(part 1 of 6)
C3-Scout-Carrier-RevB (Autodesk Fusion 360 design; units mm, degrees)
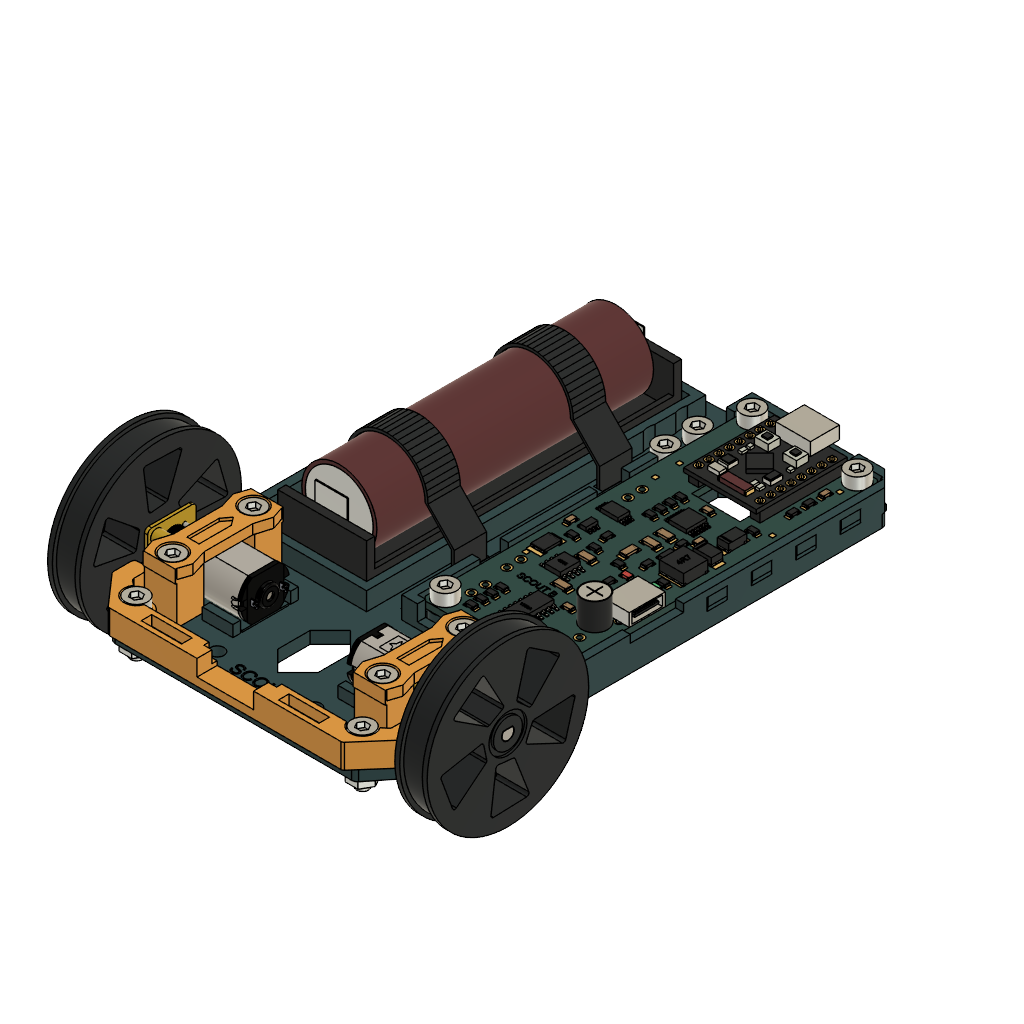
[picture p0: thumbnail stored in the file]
description: Part Number
part number: mmgm-logo-step
part number: reg28a01
part number: drv8833-dual-motor-driver-carrier-step
part number: pololu-3.3v-step-up_step-down-voltage-regulator-s7v8f3
parameter "base_thickness" = 3 comment "Floor thickness"
parameter "wheel_diameter" = 40 comment "Outside diameter"
parameter "wheel_width" = 8 comment "Wheel width"
parameter "shaft_bore" = 3.15 comment "Print coupon before wheels"
parameter "d280" = 1.35
parameter "d466" = 2.4
base_feature "Base Feature1" sketch "Bottom plated annuli 0.95 profiles"
sketch "Tapered monocoque floor outline" plane through (0, 0, 0) normal (0, 0, 1) x axis (1, 0, 0)
  line L1 (30, -53) -> (-30, -53)
  line L2 (38, -43) -> (30, -53)
  line L3 (38, -19) -> (38, -43)
  line L4 (36, -8) -> (38, -19)
  line L5 (36, 50) -> (36, -8)
  line L6 (28, 68) -> (36, 50)
  line L7 (-28, 68) -> (28, 68)
  line L8 (-36, 50) -> (-28, 68)
  line L9 (-36, -8) -> (-36, 50)
  line L10 (-38, -19) -> (-36, -8)
  line L11 (-38, -43) -> (-38, -19)
  line L12 (-30, -53) -> (-38, -43)
extrude "Extrude1" new body sketch "Tapered monocoque floor outline" along normal blind 3 (= "base_thickness")
fillet "Fillet1" radius 2
sketch "Side gill 1 outline" plane through (0, 0, 0) normal (0, 0, 1) x axis (1, 0, 0)
  line L1 (33.5, -8) -> (30.3, -10)
  line L2 (33.5, -3) -> (33.5, -8)
  line L3 (30.3, -5) -> (33.5, -3)
  line L4 (30.3, -10) -> (30.3, -5)
extrude "Extrude2" cut sketch "Side gill 1 outline" along normal blind 3
sketch "Side gill 2 outline" plane through (0, 0, 0) normal (0, 0, 1) x axis (1, 0, 0)
  line L1 (33.5, 5) -> (30.3, 3)
  line L2 (33.5, 10) -> (33.5, 5)
  line L3 (30.3, 8) -> (33.5, 10)
  line L4 (30.3, 3) -> (30.3, 8)
extrude "Extrude3" cut sketch "Side gill 2 outline" along normal blind 3
sketch "Side gill 3 outline" plane through (0, 0, 0) normal (0, 0, 1) x axis (1, 0, 0)
  line L1 (33.5, 18) -> (30.3, 16)
  line L2 (33.5, 23) -> (33.5, 18)
  line L3 (30.3, 21) -> (33.5, 23)
  line L4 (30.3, 16) -> (30.3, 21)
extrude "Extrude4" cut sketch "Side gill 3 outline" along normal blind 3
sketch "Side gill 4 outline" plane through (0, 0, 0) normal (0, 0, 1) x axis (1, 0, 0)
  line L1 (33.5, 31) -> (30.3, 29)
  line L2 (33.5, 36) -> (33.5, 31)
  line L3 (30.3, 34) -> (33.5, 36)
  line L4 (30.3, 29) -> (30.3, 34)
extrude "Extrude5" cut sketch "Side gill 4 outline" along normal blind 3
sketch "Side gill 5 outline" plane through (0, 0, 0) normal (0, 0, 1) x axis (1, 0, 0)
  line L1 (33.5, 44) -> (30.3, 42)
  line L2 (33.5, 49) -> (33.5, 44)
  line L3 (30.3, 47) -> (33.5, 49)
  line L4 (30.3, 42) -> (30.3, 47)
extrude "Extrude6" cut sketch "Side gill 5 outline" along normal blind 3
sketch "Battery floor window 1 outline" plane through (0, 0, 0) normal (0, 0, 1) x axis (1, 0, 0)
  line L1 (-7, -12) -> (-25, -12)
  line L2 (-7, -2) -> (-7, -12)
  line L3 (-10, 0) -> (-7, -2)
  line L4 (-25, 0) -> (-10, 0)
  line L5 (-25, -12) -> (-25, 0)
extrude "Extrude7" cut sketch "Battery floor window 1 outline" along normal blind 3
sketch "Battery floor window 2 outline" plane through (0, 0, 0) normal (0, 0, 1) x axis (1, 0, 0)
  line L1 (-7, 11) -> (-25, 11)
  line L2 (-7, 24) -> (-7, 11)
  line L3 (-10, 26) -> (-7, 24)
  line L4 (-25, 26) -> (-10, 26)
  line L5 (-25, 11) -> (-25, 26)
extrude "Extrude8" cut sketch "Battery floor window 2 outline" along normal blind 3
sketch "Battery floor window 3 outline" plane through (0, 0, 0) normal (0, 0, 1) x axis (1, 0, 0)
  line L1 (-7, 29) -> (-25, 29)
  line L2 (-7, 34) -> (-7, 29)
  line L3 (-10, 36) -> (-7, 34)
  line L4 (-25, 36) -> (-10, 36)
  line L5 (-25, 29) -> (-25, 36)
extrude "Extrude9" cut sketch "Battery floor window 3 outline" along normal blind 3
sketch "Battery floor window 4 outline" plane through (0, 0, 0) normal (0, 0, 1) x axis (1, 0, 0)
  line L1 (-7, 47) -> (-25, 47)
  line L2 (-7, 58) -> (-7, 47)
  line L3 (-10, 60) -> (-7, 58)
  line L4 (-25, 60) -> (-10, 60)
  line L5 (-25, 47) -> (-25, 60)
extrude "Extrude10" cut sketch "Battery floor window 4 outline" along normal blind 3
sketch "Electronics cable window 1 outline" plane through (0, 0, 0) normal (0, 0, 1) x axis (1, 0, 0)
  line L1 (25, -11) -> (12, -11)
  line L2 (27, -9) -> (25, -11)
  line L3 (27, 8) -> (27, -9)
  line L4 (12, 8) -> (27, 8)
  line L5 (12, -11) -> (12, 8)
extrude "Extrude11" cut sketch "Electronics cable window 1 outline" along normal blind 3
sketch "Electronics cable window 2 outline" plane through (0, 0, 0) normal (0, 0, 1) x axis (1, 0, 0)
  line L1 (25, 18) -> (12, 18)
  line L2 (27, 20) -> (25, 18)
  line L3 (27, 31) -> (27, 20)
  line L4 (12, 31) -> (27, 31)
  line L5 (12, 18) -> (12, 31)
extrude "Extrude12" cut sketch "Electronics cable window 2 outline" along normal blind 3
sketch "Electronics cable window 3 outline" plane through (0, 0, 0) normal (0, 0, 1) x axis (1, 0, 0)
  line L1 (25, 45) -> (12, 45)
  line L2 (27, 47) -> (25, 45)
  line L3 (27, 59) -> (27, 47)
  line L4 (12, 59) -> (27, 59)
  line L5 (12, 45) -> (12, 59)
extrude "Extrude13" cut sketch "Electronics cable window 3 outline" along normal blind 3
work_plane "WorkPlane1" AlongDistance 3 ExtraOffset 0
sketch "Sculpted side rail -1 outline" plane through (0, 0, 3) normal (0, 0, 1) x axis (1, 0, 0)
  line L1 (-36, -14) -> (-33.8, -14)
  line L2 (-36, 49) -> (-36, -14)
  line L3 (-29, 64) -> (-36, 49)
  line L4 (-27, 64) -> (-29, 64)
  line L5 (-33.8, 48) -> (-27, 64)
  line L6 (-33.8, -14) -> (-33.8, 48)
extrude "Extrude14" add sketch "Sculpted side rail -1 outline" along normal blind 4.5
work_plane "WorkPlane2" AlongDistance 3 ExtraOffset 0
sketch "Sculpted side rail 1 outline" plane through (0, 0, 3) normal (0, 0, 1) x axis (1, 0, 0)
  line L1 (36, -14) -> (33.8, -14)
  line L2 (36, 49) -> (36, -14)
  line L3 (29, 64) -> (36, 49)
  line L4 (27, 64) -> (29, 64)
  line L5 (33.8, 48) -> (27, 64)
  line L6 (33.8, -14) -> (33.8, 48)
extrude "Extrude15" add sketch "Sculpted side rail 1 outline" along normal blind 4.5
work_plane "WorkPlane3" AlongDistance 3 ExtraOffset 0
sketch "Battery longitudinal rail profile" plane through (0, 0, 3) normal (0, 0, 1) x axis (1, 0, 0)
  line L1 (-28, -17) -> (-30, -17)
  line L2 (-28, 65) -> (-28, -17)
  line L3 (-30, 65) -> (-28, 65)
  line L4 (-30, -17) -> (-30, 65)
extrude "Extrude16" add sketch "Battery longitudinal rail profile" along normal blind 4.5
work_plane "WorkPlane4" AlongDistance 3 ExtraOffset 0
sketch "Battery longitudinal rail profile (1)" plane through (0, 0, 3) normal (0, 0, 1) x axis (1, 0, 0)
  line L1 (-2, -17) -> (-4, -17)
  line L2 (-2, 65) -> (-2, -17)
  line L3 (-4, 65) -> (-2, 65)
  line L4 (-4, -17) -> (-4, 65)
extrude "Extrude17" add sketch "Battery longitudinal rail profile (1)" along normal blind 4.5
work_plane "WorkPlane5" AlongDistance 3 ExtraOffset 0
sketch "Battery end saddle profile" plane through (0, 0, 3) normal (0, 0, 1) x axis (1, 0, 0)
  line L1 (-2, -18) -> (-30, -18)
  line L2 (-2, -16) -> (-2, -18)
  line L3 (-30, -16) -> (-2, -16)
  line L4 (-30, -18) -> (-30, -16)
extrude "Extrude18" add sketch "Battery end saddle profile" along normal blind 4.5
work_plane "WorkPlane6" AlongDistance 3 ExtraOffset 0
sketch "Battery end saddle profile (1)" plane through (0, 0, 3) normal (0, 0, 1) x axis (1, 0, 0)
  line L1 (-2, 64) -> (-30, 64)
  line L2 (-2, 66) -> (-2, 64)
  line L3 (-30, 66) -> (-2, 66)
  line L4 (-30, 64) -> (-30, 66)
extrude "Extrude19" add sketch "Battery end saddle profile (1)" along normal blind 4.5
work_plane "WorkPlane7" AlongDistance 3 ExtraOffset 0
sketch "N20 seating pad -1 profile" plane through (0, 0, 3) normal (0, 0, 1) x axis (1, 0, 0)
  line L1 (-13, -37.8) -> (-37, -37.8)
  line L2 (-13, -26.2) -> (-13, -37.8)
  line L3 (-37, -26.2) -> (-13, -26.2)
  line L4 (-37, -37.8) -> (-37, -26.2)
extrude "Extrude20" add sketch "N20 seating pad -1 profile" along normal blind 0.4
work_plane "WorkPlane8" AlongDistance 3 ExtraOffset 0
sketch "Motor lateral locator profile" plane through (0, 0, 3) normal (0, 0, 1) x axis (1, 0, 0)
  line L1 (-31.4, -40.1) -> (-37, -40.1)
  line L2 (-31.4, -38.2) -> (-31.4, -40.1)
  line L3 (-37, -38.2) -> (-31.4, -38.2)
  line L4 (-37, -40.1) -> (-37, -38.2)
extrude "Extrude21" add sketch "Motor lateral locator profile" along normal blind 2.8
work_plane "WorkPlane9" AlongDistance 3 ExtraOffset 0
sketch "Motor lateral locator profile (1)" plane through (0, 0, 3) normal (0, 0, 1) x axis (1, 0, 0)
  line L1 (-31.4, -25.8) -> (-37, -25.8)
  line L2 (-31.4, -23.9) -> (-31.4, -25.8)
  line L3 (-37, -23.9) -> (-31.4, -23.9)
  line L4 (-37, -25.8) -> (-37, -23.9)
extrude "Extrude22" add sketch "Motor lateral locator profile (1)" along normal blind 2.8
work_plane "WorkPlane10" AlongDistance 3 ExtraOffset 0
sketch "Motor lateral locator profile (2)" plane through (0, 0, 3) normal (0, 0, 1) x axis (1, 0, 0)
  line L1 (-13, -40.1) -> (-20.6, -40.1)
  line L2 (-13, -38.2) -> (-13, -40.1)
  line L3 (-20.6, -38.2) -> (-13, -38.2)
  line L4 (-20.6, -40.1) -> (-20.6, -38.2)
extrude "Extrude23" add sketch "Motor lateral locator profile (2)" along normal blind 2.8
work_plane "WorkPlane11" AlongDistance 3 ExtraOffset 0
sketch "Motor lateral locator profile (3)" plane through (0, 0, 3) normal (0, 0, 1) x axis (1, 0, 0)
  line L1 (-13, -25.8) -> (-20.6, -25.8)
  line L2 (-13, -23.9) -> (-13, -25.8)
  line L3 (-20.6, -23.9) -> (-13, -23.9)
  line L4 (-20.6, -25.8) -> (-20.6, -23.9)
extrude "Extrude24" add sketch "Motor lateral locator profile (3)" along normal blind 2.8
work_plane "WorkPlane12" AlongDistance 3 ExtraOffset 0
sketch "N20 seating pad 1 profile" plane through (0, 0, 3) normal (0, 0, 1) x axis (1, 0, 0)
  line L1 (37, -37.8) -> (13, -37.8)
  line L2 (37, -26.2) -> (37, -37.8)
  line L3 (13, -26.2) -> (37, -26.2)
  line L4 (13, -37.8) -> (13, -26.2)
extrude "Extrude25" add sketch "N20 seating pad 1 profile" along normal blind 0.4
work_plane "WorkPlane13" AlongDistance 3 ExtraOffset 0
sketch "Motor lateral locator profile (4)" plane through (0, 0, 3) normal (0, 0, 1) x axis (1, 0, 0)
  line L1 (20.6, -40.1) -> (13, -40.1)
  line L2 (20.6, -38.2) -> (20.6, -40.1)
  line L3 (13, -38.2) -> (20.6, -38.2)
  line L4 (13, -40.1) -> (13, -38.2)
extrude "Extrude26" add sketch "Motor lateral locator profile (4)" along normal blind 2.8
work_plane "WorkPlane14" AlongDistance 3 ExtraOffset 0
sketch "Motor lateral locator profile (5)" plane through (0, 0, 3) normal (0, 0, 1) x axis (1, 0, 0)
  line L1 (20.6, -25.8) -> (13, -25.8)
  line L2 (20.6, -23.9) -> (20.6, -25.8)
  line L3 (13, -23.9) -> (20.6, -23.9)
  line L4 (13, -25.8) -> (13, -23.9)
extrude "Extrude27" add sketch "Motor lateral locator profile (5)" along normal blind 2.8
work_plane "WorkPlane15" AlongDistance 3 ExtraOffset 0
sketch "Motor lateral locator profile (6)" plane through (0, 0, 3) normal (0, 0, 1) x axis (1, 0, 0)
  line L1 (37, -40.1) -> (31.4, -40.1)
  line L2 (37, -38.2) -> (37, -40.1)
  line L3 (31.4, -38.2) -> (37, -38.2)
  line L4 (31.4, -40.1) -> (31.4, -38.2)
extrude "Extrude28" add sketch "Motor lateral locator profile (6)" along normal blind 2.8
work_plane "WorkPlane16" AlongDistance 3 ExtraOffset 0
sketch "Motor lateral locator profile (7)" plane through (0, 0, 3) normal (0, 0, 1) x axis (1, 0, 0)
  line L1 (37, -25.8) -> (31.4, -25.8)
  line L2 (37, -23.9) -> (37, -25.8)
  line L3 (31.4, -23.9) -> (37, -23.9)
  line L4 (31.4, -25.8) -> (31.4, -23.9)
extrude "Extrude29" add sketch "Motor lateral locator profile (7)" along normal blind 2.8
sketch "Clamp screw clearance profile" plane through (0, 0, 0) normal (0, 0, 1) x axis (1, 0, 0)
  circle C1 centre (-26, -42) radius 1.4
  circle C2 centre (-26, -22) radius 1.4
  circle C3 centre (26, -42) radius 1.4
  circle C4 centre (26, -22) radius 1.4
extrude "Extrude30" cut sketch "Clamp screw clearance profile" along normal blind 3
work_plane "WorkPlane17" AlongDistance 3 ExtraOffset 0
sketch "Electronics mounting land profile" plane through (0, 0, 3) normal (0, 0, 1) x axis (1, 0, 0)
  line L1 (30, -15) -> (7, -15)
  line L2 (30, -11) -> (30, -15)
  line L3 (7, -11) -> (30, -11)
  line L4 (7, -15) -> (7, -11)
extrude "Extrude31" add sketch "Electronics mounting land profile" along normal blind 1.5
work_plane "WorkPlane18" AlongDistance 3 ExtraOffset 0
sketch "Electronics mounting land profile (1)" plane through (0, 0, 3) normal (0, 0, 1) x axis (1, 0, 0)
  line L1 (30, 9) -> (7, 9)
  line L2 (30, 13) -> (30, 9)
  line L3 (7, 13) -> (30, 13)
  line L4 (7, 9) -> (7, 13)
extrude "Extrude32" add sketch "Electronics mounting land profile (1)" along normal blind 1.5
work_plane "WorkPlane19" AlongDistance 3 ExtraOffset 0
sketch "Electronics mounting land profile (2)" plane through (0, 0, 3) normal (0, 0, 1) x axis (1, 0, 0)
  line L1 (30, 15) -> (7, 15)
  line L2 (30, 18) -> (30, 15)
  line L3 (7, 18) -> (30, 18)
  line L4 (7, 15) -> (7, 18)
extrude "Extrude33" add sketch "Electronics mounting land profile (2)" along normal blind 1.5
work_plane "WorkPlane20" AlongDistance 3 ExtraOffset 0
sketch "Electronics mounting land profile (3)" plane through (0, 0, 3) normal (0, 0, 1) x axis (1, 0, 0)
  line L1 (30, 32) -> (7, 32)
  line L2 (30, 35) -> (30, 32)
  line L3 (7, 35) -> (30, 35)
  line L4 (7, 32) -> (7, 35)
extrude "Extrude34" add sketch "Electronics mounting land profile (3)" along normal blind 1.5
work_plane "WorkPlane21" AlongDistance 3 ExtraOffset 0
sketch "Electronics mounting land profile (4)" plane through (0, 0, 3) normal (0, 0, 1) x axis (1, 0, 0)
  line L1 (30, 41) -> (7, 41)
  line L2 (30, 45) -> (30, 41)
  line L3 (7, 45) -> (30, 45)
  line L4 (7, 41) -> (7, 45)
extrude "Extrude35" add sketch "Electronics mounting land profile (4)" along normal blind 1.5
work_plane "WorkPlane22" AlongDistance 3 ExtraOffset 0
sketch "Electronics mounting land profile (5)" plane through (0, 0, 3) normal (0, 0, 1) x axis (1, 0, 0)
  line L1 (30, 60) -> (7, 60)
  line L2 (30, 64) -> (30, 60)
  line L3 (7, 64) -> (30, 64)
  line L4 (7, 60) -> (7, 64)
extrude "Extrude36" add sketch "Electronics mounting land profile (5)" along normal blind 1.5
sketch "Battery retention passages" plane through (0, 0, 0) normal (0, 0, 1) x axis (1, 0, 0)
  line L1 (-30.8, 1) -> (-33, 1)
  line L2 (-30.8, 9) -> (-30.8, 1)
  line L3 (-33, 9) -> (-30.8, 9)
  line L4 (-33, 1) -> (-33, 9)
  line L5 (1.4, 1) -> (-0.8, 1)
  line L6 (1.4, 9) -> (1.4, 1)
  line L7 (-0.8, 9) -> (1.4, 9)
  line L8 (-0.8, 1) -> (-0.8, 9)
  line L9 (-30.8, 37) -> (-33, 37)
  line L10 (-30.8, 45) -> (-30.8, 37)
  line L11 (-33, 45) -> (-30.8, 45)
  line L12 (-33, 37) -> (-33, 45)
  line L13 (1.4, 37) -> (-0.8, 37)
  line L14 (1.4, 45) -> (1.4, 37)
  line L15 (-0.8, 45) -> (1.4, 45)
  line L16 (-0.8, 37) -> (-0.8, 45)
extrude "Extrude37" cut sketch "Battery retention passages" along normal blind 3
sketch "Electronics retention passages" plane through (0, 0, 0) normal (0, 0, 1) x axis (1, 0, 0)
  line L1 (5.3, -5) -> (3.1, -5)
  line L2 (5.3, 1) -> (5.3, -5)
  line L3 (3.1, 1) -> (5.3, 1)
  line L4 (3.1, -5) -> (3.1, 1)
  line L5 (5.3, 22) -> (3.1, 22)
  line L6 (5.3, 28) -> (5.3, 22)
  line L7 (3.1, 28) -> (5.3, 28)
  line L8 (3.1, 22) -> (3.1, 28)
  line L9 (5.3, 49) -> (3.1, 49)
  line L10 (5.3, 55) -> (5.3, 49)
  line L11 (3.1, 55) -> (5.3, 55)
  line L12 (3.1, 49) -> (3.1, 55)
extrude "Extrude38" cut sketch "Electronics retention passages" along normal blind 3
sketch "Bumper mounting M3 profile" plane through (0, 0, 0) normal (0, 0, 1) x axis (1, 0, 0)
  circle C1 centre (-28, -49) radius 1.6
  circle C2 centre (28, -49) radius 1.6
extrude "Extrude39" cut sketch "Bumper mounting M3 profile" along normal blind 3
sketch "Skid mounting M3 profile" plane through (0, 0, 0) normal (0, 0, 1) x axis (1, 0, 0)
  circle C1 centre (2, 52) radius 1.6
  circle C2 centre (2, 60) radius 1.6
extrude "Extrude40" cut sketch "Skid mounting M3 profile" along normal blind 3
sketch "Front accessory M3 profile" plane through (0, 0, 0) normal (0, 0, 1) x axis (1, 0, 0)
  circle C1 centre (-12, -45) radius 1.6
  circle C2 centre (12, -45) radius 1.6
extrude "Extrude41" cut sketch "Front accessory M3 profile" along normal blind 3
sketch "Center diamond window outline" plane through (0, 0, 0) normal (0, 0, 1) x axis (1, 0, 0)
  line L1 (0, -42) -> (-5, -37)
  line L2 (5, -37) -> (0, -42)
  line L3 (5, -29) -> (5, -37)
  line L4 (0, -24) -> (5, -29)
  line L5 (-5, -29) -> (0, -24)
  line L6 (-5, -37) -> (-5, -29)
extrude "Extrude42" cut sketch "Center diamond window outline" along normal blind 3
sketch "Swept front bumper outline" plane through (0, 0, 0) normal (0, 0, 1) x axis (1, 0, 0)
  line L1 (-36, -47) -> (-36, -41.5)
  line L2 (-29, -55) -> (-36, -47)
  line L3 (29, -55) -> (-29, -55)
  line L4 (36, -47) -> (29, -55)
  line L5 (36, -41.5) -> (36, -47)
  line L6 (32, -41.5) -> (36, -41.5)
  line L7 (32, -46) -> (32, -41.5)
  line L8 (27, -50) -> (32, -46)
  line L9 (-27, -50) -> (27, -50)
  line L10 (-32, -46) -> (-27, -50)
  line L11 (-32, -41.5) -> (-32, -46)
  line L12 (-36, -41.5) -> (-32, -41.5)
extrude "Extrude1" new body sketch "Swept front bumper outline" along normal blind 6
fillet "Fillet1" radius 0.8
sketch "Mounting ear profile" plane through (0, 0, 0) normal (0, 0, 1) x axis (1, 0, 0)
  circle C1 centre (-28, -49) radius 3.5
extrude "Extrude2" add sketch "Mounting ear profile" along normal blind 3
sketch "Mounting ear profile (1)" plane through (0, 0, 0) normal (0, 0, 1) x axis (1, 0, 0)
  circle C1 centre (28, -49) radius 3.5
extrude "Extrude3" add sketch "Mounting ear profile (1)" along normal blind 3
sketch "Bumper fasteners profile" plane through (0, 0, 0) normal (0, 0, 1) x axis (1, 0, 0)
  circle C1 centre (-28, -49) radius 1.6
  circle C2 centre (28, -49) radius 1.6
extrude "Extrude4" cut sketch "Bumper fasteners profile" along normal blind 6
work_plane "WorkPlane1" AlongDistance 3.5 ExtraOffset 0
sketch "Bumper grille recess profile" plane through (0, 0, 3.5) normal (0, 0, 1) x axis (1, 0, 0)
  line L1 (-12, -53.8) -> (-22, -53.8)
  line L2 (-12, -51.2) -> (-12, -53.8)
  line L3 (-22, -51.2) -> (-12, -51.2)
  line L4 (-22, -53.8) -> (-22, -51.2)
extrude "Extrude5" cut sketch "Bumper grille recess profile" along normal blind 2.5
work_plane "WorkPlane2" AlongDistance 3.5 ExtraOffset 0
sketch "Bumper grille recess profile (1)" plane through (0, 0, 3.5) normal (0, 0, 1) x axis (1, 0, 0)
  line L1 (5, -53.8) -> (-5, -53.8)
  line L2 (5, -51.2) -> (5, -53.8)
  line L3 (-5, -51.2) -> (5, -51.2)
  line L4 (-5, -53.8) -> (-5, -51.2)
extrude "Extrude6" cut sketch "Bumper grille recess profile (1)" along normal blind 2.5
work_plane "WorkPlane3" AlongDistance 3.5 ExtraOffset 0
sketch "Bumper grille recess profile (2)" plane through (0, 0, 3.5) normal (0, 0, 1) x axis (1, 0, 0)
  line L1 (22, -53.8) -> (12, -53.8)
  line L2 (22, -51.2) -> (22, -53.8)
  line L3 (12, -51.2) -> (22, -51.2)
  line L4 (12, -53.8) -> (12, -51.2)
extrude "Extrude7" cut sketch "Bumper grille recess profile (2)" along normal blind 2.5
work_plane "WorkPlane1" AlongDistance 10.4 ExtraOffset 0
sketch "Tapered clamp bridge outline" plane through (0, 0, 10.4) normal (0, 0, 1) x axis (1, 0, 0)
  line L1 (4, -13) -> (-4, -13)
  line L2 (5, -10) -> (4, -13)
  line L3 (3.8, -6) -> (5, -10)
  line L4 (3.8, 6) -> (3.8, -6)
  line L5 (5, 10) -> (3.8, 6)
  line L6 (4, 13) -> (5, 10)
  line L7 (-4, 13) -> (4, 13)
  line L8 (-5, 10) -> (-4, 13)
  line L9 (-3.8, 6) -> (-5, 10)
  line L10 (-3.8, -6) -> (-3.8, 6)
  line L11 (-5, -10) -> (-3.8, -6)
  line L12 (-4, -13) -> (-5, -10)
extrude "Extrude1" new body sketch "Tapered clamp bridge outline" along normal blind 2.4
sketch "Clamp foot profile" plane through (0, 0, 0) normal (0, 0, 1) x axis (1, 0, 0)
  line L1 (4, -13) -> (-4, -13)
  line L2 (4, -6.3) -> (4, -13)
  line L3 (-4, -6.3) -> (4, -6.3)
  line L4 (-4, -13) -> (-4, -6.3)
extrude "Extrude2" add sketch "Clamp foot profile" along normal blind 10.4
sketch "Clamp foot profile (1)" plane through (0, 0, 0) normal (0, 0, 1) x axis (1, 0, 0)
  line L1 (4, 6.3) -> (-4, 6.3)
  line L2 (4, 13) -> (4, 6.3)
  line L3 (-4, 13) -> (4, 13)
  line L4 (-4, 6.3) -> (-4, 13)
extrude "Extrude3" add sketch "Clamp foot profile (1)" along normal blind 10.4
sketch "M2.5 through holes profile" plane through (0, 0, 0) normal (0, 0, 1) x axis (1, 0, 0)
  circle C1 centre (0, -10) radius 1.4
  circle C2 centre (0, 10) radius 1.4
extrude "Extrude4" cut sketch "M2.5 through holes profile" along normal blind 12.8
work_plane "WorkPlane2" AlongDistance 11.6 ExtraOffset 0
sketch "Recessed screw head seats profile" plane through (0, 0, 11.6) normal (0, 0, 1) x axis (1, 0, 0)
  circle C1 centre (0, -10) radius 2.6
  circle C2 centre (0, 10) radius 2.6
extrude "Extrude5" cut sketch "Recessed screw head seats profile" along normal blind 1.2
work_plane "WorkPlane3" AlongDistance 12.8 ExtraOffset 0
sketch "Spine detail outline" plane through (0, 0, 12.8) normal (0, 0, 1) x axis (1, 0, 0)
  line L1 (1.5, -5) -> (-1.5, -5)
  line L2 (1.5, 3) -> (1.5, -5)
  line L3 (0, 5) -> (1.5, 3)
  line L4 (-1.5, 3) -> (0, 5)
  line L5 (-1.5, -5) -> (-1.5, 3)
work_plane "WorkPlane1" AlongDistance 10.4 ExtraOffset 0
sketch "Tapered clamp bridge outline" plane through (0, 0, 10.4) normal (0, 0, 1) x axis (1, 0, 0)
  line L1 (4, -13) -> (-4, -13)
  line L2 (5, -10) -> (4, -13)
  line L3 (3.8, -6) -> (5, -10)
  line L4 (3.8, 6) -> (3.8, -6)
  line L5 (5, 10) -> (3.8, 6)
  line L6 (4, 13) -> (5, 10)
  line L7 (-4, 13) -> (4, 13)
  line L8 (-5, 10) -> (-4, 13)
  line L9 (-3.8, 6) -> (-5, 10)
  line L10 (-3.8, -6) -> (-3.8, 6)
  line L11 (-5, -10) -> (-3.8, -6)
  line L12 (-4, -13) -> (-5, -10)
extrude "Extrude1" new body sketch "Tapered clamp bridge outline" along normal blind 2.4
sketch "Clamp foot profile" plane through (0, 0, 0) normal (0, 0, 1) x axis (1, 0, 0)
  line L1 (4, -13) -> (-4, -13)
  line L2 (4, -6.3) -> (4, -13)
  line L3 (-4, -6.3) -> (4, -6.3)
  line L4 (-4, -13) -> (-4, -6.3)
extrude "Extrude2" add sketch "Clamp foot profile" along normal blind 10.4
sketch "Clamp foot profile (1)" plane through (0, 0, 0) normal (0, 0, 1) x axis (1, 0, 0)
  line L1 (4, 6.3) -> (-4, 6.3)
  line L2 (4, 13) -> (4, 6.3)
  line L3 (-4, 13) -> (4, 13)
  line L4 (-4, 6.3) -> (-4, 13)
extrude "Extrude3" add sketch "Clamp foot profile (1)" along normal blind 10.4
sketch "M2.5 through holes profile" plane through (0, 0, 0) normal (0, 0, 1) x axis (1, 0, 0)
  circle C1 centre (0, -10) radius 1.4
  circle C2 centre (0, 10) radius 1.4
extrude "Extrude4" cut sketch "M2.5 through holes profile" along normal blind 12.8
work_plane "WorkPlane2" AlongDistance 11.6 ExtraOffset 0
sketch "Recessed screw head seats profile" plane through (0, 0, 11.6) normal (0, 0, 1) x axis (1, 0, 0)
  circle C1 centre (0, -10) radius 2.6
  circle C2 centre (0, 10) radius 2.6
extrude "Extrude5" cut sketch "Recessed screw head seats profile" along normal blind 1.2
work_plane "WorkPlane3" AlongDistance 12.8 ExtraOffset 0
sketch "Spine detail outline" plane through (0, 0, 12.8) normal (0, 0, 1) x axis (1, 0, 0)
  line L1 (1.5, -5) -> (-1.5, -5)
  line L2 (1.5, 3) -> (1.5, -5)
  line L3 (0, 5) -> (1.5, 3)
  line L4 (-1.5, 3) -> (0, 5)
  line L5 (-1.5, -5) -> (-1.5, 3)
sketch "Wheel blank profile" plane through (0, 0, 0) normal (0, 0, 1) x axis (1, 0, 0)
  circle C1 centre (0, 0) radius 20
extrude "Extrude1" new body sketch "Wheel blank profile" along a picked direction blind 8 (= "wheel_width")
sketch "3.15 mm D-shaft bore profile" plane through (0, 0, 0) normal (0, 0, 1) x axis (1, 0, 0)
  line L1 (1.075, 1.1511) -> (1.075, -1.1511)
  arc A1 centre (0, 0) radius 1.575 clockwise from (1.075, -1.1511) to (1.075, 1.1511)
  dimension "d195" radius A1 = 1.575 (= "shaft_bore / 2")
extrude "Extrude2" cut sketch "3.15 mm D-shaft bore profile" along a picked direction blind 8
sketch "Swept spoke window 1 outline" plane through (0, 0, 0) normal (0, 0, 1) x axis (1, 0, 0)
  line L1 (15.6631, 6.0751) -> (6.1393, 0.8652)
  line L2 (9.6351, 13.7624) -> (15.6631, 6.0751)
  line L3 (3.854, 4.8566) -> (9.6351, 13.7624)
  line L4 (6.1393, 0.8652) -> (3.854, 4.8566)
extrude "Extrude3" cut sketch "Swept spoke window 1 outline" along a picked direction blind 8
sketch "Swept spoke window 2 outline" plane through (0, 0, 0) normal (0, 0, 1) x axis (1, 0, 0)
  line L1 (-0.9376, 16.7738) -> (1.0743, 6.1062)
  line L2 (-10.1114, 13.4164) -> (-0.9376, 16.7738)
  line L3 (-3.428, 5.1661) -> (-10.1114, 13.4164)
  line L4 (1.0743, 6.1062) -> (-3.428, 5.1661)
extrude "Extrude4" cut sketch "Swept spoke window 2 outline" along a picked direction blind 8
sketch "Swept spoke window 3 outline" plane through (0, 0, 0) normal (0, 0, 1) x axis (1, 0, 0)
  line L1 (-16.2426, 4.2916) -> (-5.4754, 2.9087)
  line L2 (-15.8843, -5.4706) -> (-16.2426, 4.2916)
  line L3 (-5.9726, -1.6638) -> (-15.8843, -5.4706)
  line L4 (-5.4754, 2.9087) -> (-5.9726, -1.6638)
extrude "Extrude5" cut sketch "Swept spoke window 3 outline" along a picked direction blind 8
sketch "Swept spoke window 4 outline" plane through (0, 0, 0) normal (0, 0, 1) x axis (1, 0, 0)
  line L1 (-9.1008, -14.1214) -> (-4.4583, -4.3085)
  line L2 (0.2944, -16.7974) -> (-9.1008, -14.1214)
  line L3 (-0.2633, -6.1944) -> (0.2944, -16.7974)
  line L4 (-4.4583, -4.3085) -> (-0.2633, -6.1944)
extrude "Extrude6" cut sketch "Swept spoke window 4 outline" along a picked direction blind 8
sketch "Swept spoke window 5 outline" plane through (0, 0, 0) normal (0, 0, 1) x axis (1, 0, 0)
  line L1 (10.618, -13.0192) -> (2.72, -5.5715)
  line L2 (16.0663, -4.9107) -> (10.618, -13.0192)
  line L3 (5.8099, -2.1646) -> (16.0663, -4.9107)
  line L4 (2.72, -5.5715) -> (5.8099, -2.1646)
extrude "Extrude7" cut sketch "Swept spoke window 5 outline" along a picked direction blind 8
work_plane "WorkPlane1" AlongDistance 1.2 ExtraOffset 0
sketch "Tire retention channel" plane through (0, 0, 1.2) normal (0, 0, 1) x axis (1, 0, 0)
  circle C1 centre (0, 0) radius 20.2
  circle C2 centre (0, 0) radius 19
extrude "Extrude8" cut sketch "Tire retention channel" along a picked direction blind 5.6
work_plane "WorkPlane2" AlongDistance 7.4 ExtraOffset 0
sketch "Hub face ring" plane through (0, 0, 7.4) normal (0, 0, 1) x axis (1, 0, 0)
  circle C1 centre (0, 0) radius 4.7
  circle C2 centre (0, 0) radius 3.6
extrude "Extrude9" cut sketch "Hub face ring" along a picked direction blind 0.6
sketch "Wheel blank profile" plane through (0, 0, 0) normal (0, 0, 1) x axis (1, 0, 0)
  circle C1 centre (0, 0) radius 20
extrude "Extrude1" new body sketch "Wheel blank profile" along a picked direction blind 8 (= "wheel_width")
sketch "3.15 mm D-shaft bore profile" plane through (0, 0, 0) normal (0, 0, 1) x axis (1, 0, 0)
  line L1 (1.075, 1.1511) -> (1.075, -1.1511)
  arc A1 centre (0, 0) radius 1.575 clockwise from (1.075, -1.1511) to (1.075, 1.1511)
  dimension "d218" radius A1 = 1.575 (= "shaft_bore / 2")
extrude "Extrude2" cut sketch "3.15 mm D-shaft bore profile" along a picked direction blind 8
sketch "Swept spoke window 1 outline" plane through (0, 0, 0) normal (0, 0, 1) x axis (1, 0, 0)
  line L1 (15.6631, 6.0751) -> (6.1393, 0.8652)
  line L2 (9.6351, 13.7624) -> (15.6631, 6.0751)
  line L3 (3.854, 4.8566) -> (9.6351, 13.7624)
  line L4 (6.1393, 0.8652) -> (3.854, 4.8566)
extrude "Extrude3" cut sketch "Swept spoke window 1 outline" along a picked direction blind 8
sketch "Swept spoke window 2 outline" plane through (0, 0, 0) normal (0, 0, 1) x axis (1, 0, 0)
  line L1 (-0.9376, 16.7738) -> (1.0743, 6.1062)
  line L2 (-10.1114, 13.4164) -> (-0.9376, 16.7738)
  line L3 (-3.428, 5.1661) -> (-10.1114, 13.4164)
  line L4 (1.0743, 6.1062) -> (-3.428, 5.1661)
extrude "Extrude4" cut sketch "Swept spoke window 2 outline" along a picked direction blind 8
sketch "Swept spoke window 3 outline" plane through (0, 0, 0) normal (0, 0, 1) x axis (1, 0, 0)
  line L1 (-16.2426, 4.2916) -> (-5.4754, 2.9087)
  line L2 (-15.8843, -5.4706) -> (-16.2426, 4.2916)
  line L3 (-5.9726, -1.6638) -> (-15.8843, -5.4706)
  line L4 (-5.4754, 2.9087) -> (-5.9726, -1.6638)
extrude "Extrude5" cut sketch "Swept spoke window 3 outline" along a picked direction blind 8
sketch "Swept spoke window 4 outline" plane through (0, 0, 0) normal (0, 0, 1) x axis (1, 0, 0)
  line L1 (-9.1008, -14.1214) -> (-4.4583, -4.3085)
  line L2 (0.2944, -16.7974) -> (-9.1008, -14.1214)
  line L3 (-0.2633, -6.1944) -> (0.2944, -16.7974)
  line L4 (-4.4583, -4.3085) -> (-0.2633, -6.1944)
extrude "Extrude6" cut sketch "Swept spoke window 4 outline" along a picked direction blind 8
sketch "Swept spoke window 5 outline" plane through (0, 0, 0) normal (0, 0, 1) x axis (1, 0, 0)
  line L1 (10.618, -13.0192) -> (2.72, -5.5715)
  line L2 (16.0663, -4.9107) -> (10.618, -13.0192)
  line L3 (5.8099, -2.1646) -> (16.0663, -4.9107)
  line L4 (2.72, -5.5715) -> (5.8099, -2.1646)
extrude "Extrude7" cut sketch "Swept spoke window 5 outline" along a picked direction blind 8
work_plane "WorkPlane1" AlongDistance 1.2 ExtraOffset 0
sketch "Tire retention channel" plane through (0, 0, 1.2) normal (0, 0, 1) x axis (1, 0, 0)
  circle C1 centre (0, 0) radius 20.2
  circle C2 centre (0, 0) radius 19
extrude "Extrude8" cut sketch "Tire retention channel" along a picked direction blind 5.6
work_plane "WorkPlane2" AlongDistance 7.4 ExtraOffset 0
sketch "Hub face ring" plane through (0, 0, 7.4) normal (0, 0, 1) x axis (1, 0, 0)
  circle C1 centre (0, 0) radius 4.7
  circle C2 centre (0, 0) radius 3.6
extrude "Extrude9" cut sketch "Hub face ring" along a picked direction blind 0.6
sketch "Swept skid runner outline" plane through (0, 0, 0) normal (0, 0, 1) x axis (1, 0, 0)
  line L1 (66, 0) -> (49, 0)
  line L2 (84, -6.8) -> (66, 0)
  line L3 (87, -9.2) -> (84, -6.8)
  line L4 (86, -11.6) -> (87, -9.2)
  line L5 (78, -11.6) -> (86, -11.6)
  line L6 (63, -4) -> (78, -11.6)
  line L7 (49, -4) -> (63, -4)
  line L8 (49, 0) -> (49, -4)
extrude "Extrude1" new body sketch "Swept skid runner outline" along a picked direction blind 12
sketch "Tail mounting bores" plane through (0, 0, 0) normal (0, 1, 0) x axis (1, 0, 0)
  circle C1 centre (52, -6) radius 1.6
  circle C2 centre (60, -6) radius 1.6
extrude "Extrude2" cut sketch "Tail mounting bores" along a picked direction blind -4 (= "-( 4 mm )")
sketch "Tail lightening eye outline" plane through (0, 0, 0) normal (0, 0, 1) x axis (1, 0, 0)
  line L1 (78, -7) -> (68, -3)
  line L2 (76, -8) -> (78, -7)
  line L3 (67, -4) -> (76, -8)
  line L4 (68, -3) -> (67, -4)
extrude "Extrude3" cut sketch "Tail lightening eye outline" along a picked direction blind 12
sketch "Octagonal cradle outline" plane through (0, 0, 0) normal (0, 0, 1) x axis (1, 0, 0)
  line L1 (11, -14) -> (-11, -14)
  line L2 (13, -12) -> (11, -14)
  line L3 (13, 12) -> (13, -12)
  line L4 (11, 14) -> (13, 12)
  line L5 (-11, 14) -> (11, 14)
  line L6 (-13, 12) -> (-11, 14)
  line L7 (-13, -12) -> (-13, 12)
  line L8 (-11, -14) -> (-13, -12)
extrude "Extrude1" new body sketch "Octagonal cradle outline" along normal blind 2
sketch "Open wiring well profile" plane through (0, 0, 0) normal (0, 0, 1) x axis (1, 0, 0)
  line L1 (7, -8) -> (-7, -8)
  line L2 (7, 8) -> (7, -8)
  line L3 (-7, 8) -> (7, 8)
  line L4 (-7, -8) -> (-7, 8)
extrude "Extrude2" cut sketch "Open wiring well profile" along normal blind 2
work_plane "WorkPlane1" AlongDistance 2 ExtraOffset 0
sketch "Socket end saddle profile" plane through (0, 0, 2) normal (0, 0, 1) x axis (1, 0, 0)
  line L1 (6, -11.2) -> (-6, -11.2)
  line L2 (6, -9.2) -> (6, -11.2)
  line L3 (-6, -9.2) -> (6, -9.2)
  line L4 (-6, -11.2) -> (-6, -9.2)
extrude "Extrude3" add sketch "Socket end saddle profile" along normal blind 6
work_plane "WorkPlane2" AlongDistance 2 ExtraOffset 0
sketch "Socket end saddle profile (1)" plane through (0, 0, 2) normal (0, 0, 1) x axis (1, 0, 0)
  line L1 (6, 9.2) -> (-6, 9.2)
  line L2 (6, 11.2) -> (6, 9.2)
  line L3 (-6, 11.2) -> (6, 11.2)
  line L4 (-6, 9.2) -> (-6, 11.2)
extrude "Extrude4" add sketch "Socket end saddle profile (1)" along normal blind 6
sketch "Cradle strap slots" plane through (0, 0, 0) normal (0, 0, 1) x axis (1, 0, 0)
  line L1 (-9, -4) -> (-11, -4)
  line L2 (-9, 4) -> (-9, -4)
  line L3 (-11, 4) -> (-9, 4)
  line L4 (-11, -4) -> (-11, 4)
  line L5 (11, -4) -> (9, -4)
  line L6 (11, 4) -> (11, -4)
  line L7 (9, 4) -> (11, 4)
  line L8 (9, -4) -> (9, 4)
extrude "Extrude5" cut sketch "Cradle strap slots" along normal blind 2
sketch "Coupon profile" plane through (0, 0, 0) normal (0, 0, 1) x axis (1, 0, 0)
  circle C1 centre (0, 0) radius 5
extrude "Extrude1" new body sketch "Coupon profile" along normal blind 5
sketch "Wheel fit test profile" plane through (0, 0, 0) normal (0, 0, 1) x axis (1, 0, 0)
  line L1 (1.075, 1.1511) -> (1.075, -1.1511)
  arc A1 centre (0, 0) radius 1.575 clockwise from (1.075, -1.1511) to (1.075, 1.1511)
  dimension "d261" radius A1 = 1.575 (= "shaft_bore / 2")
extrude "Extrude2" cut sketch "Wheel fit test profile" along normal blind 5
position "Position1"
sketch "SuperMini PCB 18 x 22.52 profile" plane through (0, 0, 0) normal (0, 0, 1) x axis (1, 0, 0)
  line L1 (9, -11.26) -> (-9, -11.26)
  line L2 (9, 11.26) -> (9, -11.26)
  line L3 (-9, 11.26) -> (9, 11.26)
  line L4 (-9, -11.26) -> (-9, 11.26)
extrude "Extrude1" new body sketch "SuperMini PCB 18 x 22.52 profile" along normal blind 1
sketch "Plated header through holes profile" plane through (0, 0, 0) normal (0, 0, 1) x axis (1, 0, 0)
  circle C1 centre (-7.62, -8.89) radius 0.525
  circle C2 centre (-7.62, -6.35) radius 0.525
  circle C3 centre (-7.62, -3.81) radius 0.525
  circle C4 centre (-7.62, -1.27) radius 0.525
  circle C5 centre (-7.62, 1.27) radius 0.525
  circle C6 centre (-7.62, 3.81) radius 0.525
  circle C7 centre (-7.62, 6.35) radius 0.525
  circle C8 centre (-7.62, 8.89) radius 0.525
  circle C9 centre (7.62, -8.89) radius 0.525
  circle C10 centre (7.62, -6.35) radius 0.525
  circle C11 centre (7.62, -3.81) radius 0.525
  circle C12 centre (7.62, -1.27) radius 0.525
  circle C13 centre (7.62, 1.27) radius 0.525
  circle C14 centre (7.62, 3.81) radius 0.525
  circle C15 centre (7.62, 6.35) radius 0.525
  circle C16 centre (7.62, 8.89) radius 0.525
extrude "Extrude2" cut sketch "Plated header through holes profile" along normal blind 1
work_plane "WorkPlane1" AlongDistance 1 ExtraOffset 0
sketch "Top gold annular pads profiles" plane through (0, 0, 1) normal (0, 0, 1) x axis (1, 0, 0)
  circle C1 centre (-7.62, -8.89) radius 0.95
  circle C2 centre (-7.62, -8.89) radius 0.525
  circle C3 centre (-7.62, -6.35) radius 0.95
  circle C4 centre (-7.62, -6.35) radius 0.525
  circle C5 centre (-7.62, -3.81) radius 0.95
  circle C6 centre (-7.62, -3.81) radius 0.525
  circle C7 centre (-7.62, -1.27) radius 0.95
  circle C8 centre (-7.62, -1.27) radius 0.525
  circle C9 centre (-7.62, 1.27) radius 0.95
  circle C10 centre (-7.62, 1.27) radius 0.525
  circle C11 centre (-7.62, 3.81) radius 0.95
  circle C12 centre (-7.62, 3.81) radius 0.525
  circle C13 centre (-7.62, 6.35) radius 0.95
  circle C14 centre (-7.62, 6.35) radius 0.525
  circle C15 centre (-7.62, 8.89) radius 0.95
  circle C16 centre (-7.62, 8.89) radius 0.525
  circle C17 centre (7.62, -8.89) radius 0.95
  circle C18 centre (7.62, -8.89) radius 0.525
  circle C19 centre (7.62, -6.35) radius 0.95
  circle C20 centre (7.62, -6.35) radius 0.525
  circle C21 centre (7.62, -3.81) radius 0.95
  circle C22 centre (7.62, -3.81) radius 0.525
  circle C23 centre (7.62, -1.27) radius 0.95
  circle C24 centre (7.62, -1.27) radius 0.525
  circle C25 centre (7.62, 1.27) radius 0.95
  circle C26 centre (7.62, 1.27) radius 0.525
  circle C27 centre (7.62, 3.81) radius 0.95
  circle C28 centre (7.62, 3.81) radius 0.525
  circle C29 centre (7.62, 6.35) radius 0.95
  circle C30 centre (7.62, 6.35) radius 0.525
  circle C31 centre (7.62, 8.89) radius 0.95
  circle C32 centre (7.62, 8.89) radius 0.525
extrude "Extrude3" new body sketch "Top gold annular pads profiles" along normal blind 0.04
work_plane "WorkPlane2" AlongDistance -0.04 ExtraOffset 0
sketch "Bottom gold annular pads profiles" plane through (0, 0, -0.04) normal (0, 0, 1) x axis (1, 0, 0)
  circle C1 centre (-7.62, -8.89) radius 0.95
  circle C2 centre (-7.62, -8.89) radius 0.525
  circle C3 centre (-7.62, -6.35) radius 0.95
  circle C4 centre (-7.62, -6.35) radius 0.525
  circle C5 centre (-7.62, -3.81) radius 0.95
  circle C6 centre (-7.62, -3.81) radius 0.525
  circle C7 centre (-7.62, -1.27) radius 0.95
  circle C8 centre (-7.62, -1.27) radius 0.525
  circle C9 centre (-7.62, 1.27) radius 0.95
  circle C10 centre (-7.62, 1.27) radius 0.525
  circle C11 centre (-7.62, 3.81) radius 0.95
  circle C12 centre (-7.62, 3.81) radius 0.525
  circle C13 centre (-7.62, 6.35) radius 0.95
  circle C14 centre (-7.62, 6.35) radius 0.525
  circle C15 centre (-7.62, 8.89) radius 0.95
  circle C16 centre (-7.62, 8.89) radius 0.525
  circle C17 centre (7.62, -8.89) radius 0.95
  circle C18 centre (7.62, -8.89) radius 0.525
  circle C19 centre (7.62, -6.35) radius 0.95
  circle C20 centre (7.62, -6.35) radius 0.525
  circle C21 centre (7.62, -3.81) radius 0.95
  circle C22 centre (7.62, -3.81) radius 0.525
  circle C23 centre (7.62, -1.27) radius 0.95
  circle C24 centre (7.62, -1.27) radius 0.525
  circle C25 centre (7.62, 1.27) radius 0.95
  circle C26 centre (7.62, 1.27) radius 0.525
  circle C27 centre (7.62, 3.81) radius 0.95
  circle C28 centre (7.62, 3.81) radius 0.525
  circle C29 centre (7.62, 6.35) radius 0.95
  circle C30 centre (7.62, 6.35) radius 0.525
  circle C31 centre (7.62, 8.89) radius 0.95
  circle C32 centre (7.62, 8.89) radius 0.525
extrude "Extrude4" new body sketch "Bottom gold annular pads profiles" along normal blind 0.04
work_plane "WorkPlane3" AlongDistance 1 ExtraOffset 0
sketch "USB-C metal shell profile" plane through (0, 0, 1) normal (0, 0, 1) x axis (1, 0, 0)
  line L1 (4.35, 6.8) -> (-4.35, 6.8)
  line L2 (4.35, 14) -> (4.35, 6.8)
  line L3 (-4.35, 14) -> (4.35, 14)
  line L4 (-4.35, 6.8) -> (-4.35, 14)
extrude "Extrude5" new body sketch "USB-C metal shell profile" along normal blind 3.2
work_plane "WorkPlane4" ExtraOffset 0
sketch "USB-C port cavity profile" plane through (0, 0, 1.35) normal (0, 0, 1) x axis (1, 0, 0)
  line L1 (3.8, 7.5) -> (-3.8, 7.5)
  line L2 (3.8, 14.2) -> (3.8, 7.5)
  line L3 (-3.8, 14.2) -> (3.8, 14.2)
  line L4 (-3.8, 7.5) -> (-3.8, 14.2)
extrude "Extrude6" cut sketch "USB-C port cavity profile" along normal blind 2.5
work_plane "WorkPlane5" AlongDistance 2.15 ExtraOffset 0
sketch "USB-C insulated tongue profile" plane through (0, 0, 2.15) normal (0, 0, 1) x axis (1, 0, 0)
  line L1 (3, 8.5) -> (-3, 8.5)
  line L2 (3, 13.7) -> (3, 8.5)
  line L3 (-3, 13.7) -> (3, 13.7)
  line L4 (-3, 8.5) -> (-3, 13.7)
extrude "Extrude7" new body sketch "USB-C insulated tongue profile" along normal blind 0.5
work_plane "WorkPlane6" AlongDistance 2.65 ExtraOffset 0
sketch "USB contact fingers profiles" plane through (0, 0, 2.65) normal (0, 0, 1) x axis (1, 0, 0)
  line L1 (-2.4, 11.4) -> (-2.6, 11.4)
  line L2 (-2.4, 13.4) -> (-2.4, 11.4)
  line L3 (-2.6, 13.4) -> (-2.4, 13.4)
  line L4 (-2.6, 11.4) -> (-2.6, 13.4)
  line L5 (-1.93, 11.4) -> (-2.13, 11.4)
  line L6 (-1.93, 13.4) -> (-1.93, 11.4)
  line L7 (-2.13, 13.4) -> (-1.93, 13.4)
  line L8 (-2.13, 11.4) -> (-2.13, 13.4)
  line L9 (-1.46, 11.4) -> (-1.66, 11.4)
  line L10 (-1.46, 13.4) -> (-1.46, 11.4)
  line L11 (-1.66, 13.4) -> (-1.46, 13.4)
  line L12 (-1.66, 11.4) -> (-1.66, 13.4)
  line L13 (-0.99, 11.4) -> (-1.19, 11.4)
  line L14 (-0.99, 13.4) -> (-0.99, 11.4)
  line L15 (-1.19, 13.4) -> (-0.99, 13.4)
  line L16 (-1.19, 11.4) -> (-1.19, 13.4)
  line L17 (-0.52, 11.4) -> (-0.72, 11.4)
  line L18 (-0.52, 13.4) -> (-0.52, 11.4)
  line L19 (-0.72, 13.4) -> (-0.52, 13.4)
  line L20 (-0.72, 11.4) -> (-0.72, 13.4)
  line L21 (-0.05, 11.4) -> (-0.25, 11.4)
  line L22 (-0.05, 13.4) -> (-0.05, 11.4)
  line L23 (-0.25, 13.4) -> (-0.05, 13.4)
  line L24 (-0.25, 11.4) -> (-0.25, 13.4)
  line L25 (0.42, 11.4) -> (0.22, 11.4)
  line L26 (0.42, 13.4) -> (0.42, 11.4)
  line L27 (0.22, 13.4) -> (0.42, 13.4)
  line L28 (0.22, 11.4) -> (0.22, 13.4)
  line L29 (0.89, 11.4) -> (0.69, 11.4)
  line L30 (0.89, 13.4) -> (0.89, 11.4)
  line L31 (0.69, 13.4) -> (0.89, 13.4)
  line L32 (0.69, 11.4) -> (0.69, 13.4)
  line L33 (1.36, 11.4) -> (1.16, 11.4)
  line L34 (1.36, 13.4) -> (1.36, 11.4)
  line L35 (1.16, 13.4) -> (1.36, 13.4)
  line L36 (1.16, 11.4) -> (1.16, 13.4)
  line L37 (1.83, 11.4) -> (1.63, 11.4)
  line L38 (1.83, 13.4) -> (1.83, 11.4)
  line L39 (1.63, 13.4) -> (1.83, 13.4)
  line L40 (1.63, 11.4) -> (1.63, 13.4)
  line L41 (2.3, 11.4) -> (2.1, 11.4)
  line L42 (2.3, 13.4) -> (2.3, 11.4)
  line L43 (2.1, 13.4) -> (2.3, 13.4)
  line L44 (2.1, 11.4) -> (2.1, 13.4)
  line L45 (2.77, 11.4) -> (2.57, 11.4)
  line L46 (2.77, 13.4) -> (2.77, 11.4)
  line L47 (2.57, 13.4) -> (2.77, 13.4)
  line L48 (2.57, 11.4) -> (2.57, 13.4)
extrude "Extrude8" new body sketch "USB contact fingers profiles" along normal blind 0.04
work_plane "WorkPlane7" AlongDistance 1 ExtraOffset 0
sketch "Tact switch bodies profiles" plane through (0, 0, 1) normal (0, 0, 1) x axis (1, 0, 0)
  line L1 (-1.8, 2.5) -> (-5.2, 2.5)
  line L2 (-1.8, 5.5) -> (-1.8, 2.5)
  line L3 (-5.2, 5.5) -> (-1.8, 5.5)
  line L4 (-5.2, 2.5) -> (-5.2, 5.5)
  line L5 (5.2, 2.5) -> (1.8, 2.5)
  line L6 (5.2, 5.5) -> (5.2, 2.5)
  line L7 (1.8, 5.5) -> (5.2, 5.5)
  line L8 (1.8, 2.5) -> (1.8, 5.5)
extrude "Extrude9" new body sketch "Tact switch bodies profiles" along normal blind 1.7
work_plane "WorkPlane8" AlongDistance 2.7 ExtraOffset 0
sketch "Switch plungers profiles" plane through (0, 0, 2.7) normal (0, 0, 1) x axis (1, 0, 0)
  line L1 (-2.75, 3.3) -> (-4.25, 3.3)
  line L2 (-2.75, 4.7) -> (-2.75, 3.3)
  line L3 (-4.25, 4.7) -> (-2.75, 4.7)
  line L4 (-4.25, 3.3) -> (-4.25, 4.7)
  line L5 (4.25, 3.3) -> (2.75, 3.3)
  line L6 (4.25, 4.7) -> (4.25, 3.3)
  line L7 (2.75, 4.7) -> (4.25, 4.7)
  line L8 (2.75, 3.3) -> (2.75, 4.7)
extrude "Extrude10" new body sketch "Switch plungers profiles" along normal blind 0.35
work_plane "WorkPlane9" AlongDistance 1 ExtraOffset 0
sketch "ESP32-C3 QFN body outline" plane through (0, 0, 1) normal (0, 0, 1) x axis (1, 0, 0)
  line L1 (3.4, -1.4) -> (0, 2)
  line L2 (0, -4.8) -> (3.4, -1.4)
  line L3 (-3.4, -1.4) -> (0, -4.8)
  line L4 (0, 2) -> (-3.4, -1.4)
extrude "Extrude11" new body sketch "ESP32-C3 QFN body outline" along normal blind 1
work_plane "WorkPlane10" AlongDistance 1 ExtraOffset 0
sketch "Power and crystal packages profiles" plane through (0, 0, 1) normal (0, 0, 1) x axis (1, 0, 0)
  line L1 (-3, -6.3) -> (-5.5, -6.3)
  line L2 (-3, -3.7) -> (-3, -6.3)
  line L3 (-5.5, -3.7) -> (-3, -3.7)
  line L4 (-5.5, -6.3) -> (-5.5, -3.7)
  line L5 (-2.6, -8.8) -> (-5.5, -8.8)
  line L6 (-2.6, -7) -> (-2.6, -8.8)
  line L7 (-5.5, -7) -> (-2.6, -7)
  line L8 (-5.5, -8.8) -> (-5.5, -7)
  line L9 (5.8, -4.5) -> (3.8, -4.5)
  line L10 (5.8, -1.5) -> (5.8, -4.5)
  line L11 (3.8, -1.5) -> (5.8, -1.5)
  line L12 (3.8, -4.5) -> (3.8, -1.5)
extrude "Extrude12" new body sketch "Power and crystal packages profiles" along normal blind 1
work_plane "WorkPlane11" AlongDistance 2 ExtraOffset 0
sketch "Small black ICs profiles" plane through (0, 0, 2) normal (0, 0, 1) x axis (1, 0, 0)
  line L1 (-3.2, -5.9) -> (-5.3, -5.9)
  line L2 (-3.2, -4) -> (-3.2, -5.9)
  line L3 (-5.3, -4) -> (-3.2, -4)
  line L4 (-5.3, -5.9) -> (-5.3, -4)
  line L5 (5.6, -4.3) -> (4, -4.3)
  line L6 (5.6, -1.7) -> (5.6, -4.3)
  line L7 (4, -1.7) -> (5.6, -1.7)
  line L8 (4, -4.3) -> (4, -1.7)
extrude "Extrude13" new body sketch "Small black ICs profiles" along normal blind 0.2
work_plane "WorkPlane12" AlongDistance 1 ExtraOffset 0
sketch "Ceramic passives profiles" plane through (0, 0, 1) normal (0, 0, 1) x axis (1, 0, 0)
  line L1 (-4.5, -1.3) -> (-5.5, -1.3)
  line L2 (-4.5, 0.2) -> (-4.5, -1.3)
  line L3 (-5.5, 0.2) -> (-4.5, 0.2)
  line L4 (-5.5, -1.3) -> (-5.5, 0.2)
  line L5 (-4.5, 0.7) -> (-5.5, 0.7)
  line L6 (-4.5, 1.8) -> (-4.5, 0.7)
  line L7 (-5.5, 1.8) -> (-4.5, 1.8)
  line L8 (-5.5, 0.7) -> (-5.5, 1.8)
  line L9 (5.5, 0.7) -> (4.5, 0.7)
  line L10 (5.5, 1.8) -> (5.5, 0.7)
  line L11 (4.5, 1.8) -> (5.5, 1.8)
  line L12 (4.5, 0.7) -> (4.5, 1.8)
  line L13 (4, -7) -> (3, -7)
  line L14 (4, -5.5) -> (4, -7)
  line L15 (3, -5.5) -> (4, -5.5)
  line L16 (3, -7) -> (3, -5.5)
  line L17 (5.5, -7) -> (4.5, -7)
  line L18 (5.5, -5.5) -> (5.5, -7)
  line L19 (4.5, -5.5) -> (5.5, -5.5)
  line L20 (4.5, -7) -> (4.5, -5.5)
extrude "Extrude14" new body sketch "Ceramic passives profiles" along normal blind 0.6
work_plane "WorkPlane13" AlongDistance 1 ExtraOffset 0
sketch "Ceramic antenna profile" plane through (0, 0, 1) normal (0, 0, 1) x axis (1, 0, 0)
  line L1 (4.7, -9.8) -> (-1.7, -9.8)
  line L2 (4.7, -7.6) -> (4.7, -9.8)
  line L3 (-1.7, -7.6) -> (4.7, -7.6)
  line L4 (-1.7, -9.8) -> (-1.7, -7.6)
extrude "Extrude15" new body sketch "Ceramic antenna profile" along normal blind 1.1
work_plane "WorkPlane14" AlongDistance 1 ExtraOffset 0
sketch "Antenna end metallization profiles" plane through (0, 0, 1) normal (0, 0, 1) x axis (1, 0, 0)
  line L1 (-1.6, -9.8) -> (-2, -9.8)
  line L2 (-1.6, -7.6) -> (-1.6, -9.8)
  line L3 (-2, -7.6) -> (-1.6, -7.6)
  line L4 (-2, -9.8) -> (-2, -7.6)
  line L5 (5, -9.8) -> (4.6, -9.8)
  line L6 (5, -7.6) -> (5, -9.8)
  line L7 (4.6, -7.6) -> (5, -7.6)
  line L8 (4.6, -9.8) -> (4.6, -7.6)
extrude "Extrude16" new body sketch "Antenna end metallization profiles" along normal blind 0.95
sketch "DIP socket body 20.30 x 10.02 profile" plane through (0, 0, 0) normal (0, 0, 1) x axis (1, 0, 0)
  line L1 (5.01, -10.15) -> (-5.01, -10.15)
  line L2 (5.01, 10.15) -> (5.01, -10.15)
  line L3 (-5.01, 10.15) -> (5.01, 10.15)
  line L4 (-5.01, -10.15) -> (-5.01, 10.15)
extrude "Extrude1" new body sketch "DIP socket body 20.30 x 10.02 profile" along normal blind 4.2
sketch "Open center of socket profile" plane through (0, 0, 0) normal (0, 0, 1) x axis (1, 0, 0)
  line L1 (2.1, -8.2) -> (-2.1, -8.2)
  line L2 (2.1, 8.2) -> (2.1, -8.2)
  line L3 (-2.1, 8.2) -> (2.1, 8.2)
  line L4 (-2.1, -8.2) -> (-2.1, 8.2)
extrude "Extrude2" cut sketch "Open center of socket profile" along normal blind 4.2
work_plane "WorkPlane1" AlongDistance 0.7 ExtraOffset 0
sketch "Socket contact wells profile" plane through (0, 0, 0.7) normal (0, 0, 1) x axis (1, 0, 0)
  circle C1 centre (-3.81, -8.89) radius 0.625
  circle C2 centre (-3.81, -6.35) radius 0.625
  circle C3 centre (-3.81, -3.81) radius 0.625
  circle C4 centre (-3.81, -1.27) radius 0.625
  circle C5 centre (-3.81, 1.27) radius 0.625
  circle C6 centre (-3.81, 3.81) radius 0.625
  circle C7 centre (-3.81, 6.35) radius 0.625
  circle C8 centre (-3.81, 8.89) radius 0.625
  circle C9 centre (3.81, -8.89) radius 0.625
  circle C10 centre (3.81, -6.35) radius 0.625
  circle C11 centre (3.81, -3.81) radius 0.625
  circle C12 centre (3.81, -1.27) radius 0.625
  circle C13 centre (3.81, 1.27) radius 0.625
  circle C14 centre (3.81, 3.81) radius 0.625
  circle C15 centre (3.81, 6.35) radius 0.625
  circle C16 centre (3.81, 8.89) radius 0.625
extrude "Extrude3" cut sketch "Socket contact wells profile" along normal blind 3.5
work_plane "WorkPlane2" AlongDistance 4.1 ExtraOffset 0
sketch "Machined contact rims profiles" plane through (0, 0, 4.1) normal (0, 0, 1) x axis (1, 0, 0)
  circle C1 centre (-3.81, -8.89) radius 0.6
  circle C2 centre (-3.81, -8.89) radius 0.4
  circle C3 centre (-3.81, -6.35) radius 0.6
  circle C4 centre (-3.81, -6.35) radius 0.4
  circle C5 centre (-3.81, -3.81) radius 0.6
  circle C6 centre (-3.81, -3.81) radius 0.4
  circle C7 centre (-3.81, -1.27) radius 0.6
  circle C8 centre (-3.81, -1.27) radius 0.4
  circle C9 centre (-3.81, 1.27) radius 0.6
  circle C10 centre (-3.81, 1.27) radius 0.4
  circle C11 centre (-3.81, 3.81) radius 0.6
  circle C12 centre (-3.81, 3.81) radius 0.4
  circle C13 centre (-3.81, 6.35) radius 0.6
  circle C14 centre (-3.81, 6.35) radius 0.4
  circle C15 centre (-3.81, 8.89) radius 0.6
  circle C16 centre (-3.81, 8.89) radius 0.4
  circle C17 centre (3.81, -8.89) radius 0.6
  circle C18 centre (3.81, -8.89) radius 0.4
  circle C19 centre (3.81, -6.35) radius 0.6
  circle C20 centre (3.81, -6.35) radius 0.4
  circle C21 centre (3.81, -3.81) radius 0.6
  circle C22 centre (3.81, -3.81) radius 0.4
  circle C23 centre (3.81, -1.27) radius 0.6
  circle C24 centre (3.81, -1.27) radius 0.4
  circle C25 centre (3.81, 1.27) radius 0.6
  circle C26 centre (3.81, 1.27) radius 0.4
  circle C27 centre (3.81, 3.81) radius 0.6
  circle C28 centre (3.81, 3.81) radius 0.4
  circle C29 centre (3.81, 6.35) radius 0.6
  circle C30 centre (3.81, 6.35) radius 0.4
  circle C31 centre (3.81, 8.89) radius 0.6
  circle C32 centre (3.81, 8.89) radius 0.4
extrude "Extrude4" new body sketch "Machined contact rims profiles" along normal blind 0.15
work_plane "WorkPlane3" AlongDistance -3.2 ExtraOffset 0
